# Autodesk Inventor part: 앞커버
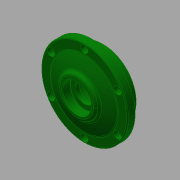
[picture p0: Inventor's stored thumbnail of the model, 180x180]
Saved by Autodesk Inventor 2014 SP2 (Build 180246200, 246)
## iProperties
Created: 2016-05
Part Number: 앞커버
Document SubType Name: Modeling
Designer: mduedu
Density: 2.71 g/cm^3
Material: 알루미늄 6061
Appearance: 진녹색
Author: mduedu
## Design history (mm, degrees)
sketch "스케치1"
  geometry: C1 r 35 at (0, 0); C2 r 45 at (0, 0); 1 further point
  constraints: 2 centre point, 2 coincident
  dimensions: "d33" = 90 diameter of C2; "d34" = 70 diameter of C1
extrude "돌출1" new body sketch "스케치1" distance "d0" = 8; taper "d1" = 0 deg
extrude "돌출2" join sketch "스케치1" distance "d2" = 8; taper "d3" = 0 deg; dims "d35" = 12, "d36" = 0
sketch "스케치5"
  geometry: L1 (-45, 8)-(45, 8) reference; L2 (0, 0)-(0, 15); L3 (-45, 0)-(45, 0) reference; L4 (35, 8)-(0, 8); A1 r 91 centre (0, -76) between (35, 8) and (0, 15)
  constraints: 4 end point, 3 point on line, 2 point on circle, 1 centre point, 1 midpoint, 1 perpendicular
  dimensions: "d37" = 35 distance from line of L2 L4.start; "d39" = 7 distance from line of L1 L2.end
revolve "회전2" sketch "스케치5" stored, may be unused: angle "d40" = 90 deg
node "작업 평면1"
sketch "스케치6"
  geometry: C1 r 20 at (0, 0); 1 further point
  constraints: 1 centre point, 1 coincident
  dimensions: "d42" = 40 diameter of C1
extrude "돌출4" join sketch "스케치6" stored distance "d43" = 10; taper "d44" = 0 deg
sketch "스케치4"
  geometry: L1 (0, -12)-(0, 16); L2 (-20, -12)-(-20, 0); L3 (-20, 0)-(-15, 0); L4 (-15, 0)-(-15, 3); L5 (-15, 3)-(-10, 3); L6 (-10, 3)-(-10, 7.5); L7 (-10, 7.5)-(-15, 7.5); L8 (-15, 7.5)-(-15, 16); L9 (35, -12)-(-35, -12) reference; L10 (-20, 16)-(20, 16) reference; 1 further point
  constraints: 16 end point, 6 parallel, 3 point on line, 2 midpoint, 1 perpendicular, 1 vertical
  dimensions: "d15" = 40 diameter of L2 L1; "d16" = 30 diameter of L8 L1; "d18" = 12 distance of L2.start L2.end; "d19" = 3 distance of L3.end L4.end; "d20" = 30 diameter of L4 L1; "d21" = 20 diameter of L6 L1; "d45" = 8.5 distance of L7.end L8.end
revolve "회전1" sketch "스케치4" stored, may be unused: angle "d22" = 90 deg
fillet "모깎기2" dims "d23" = 3
fillet "모깎기3" dims "d24" = 0.3
chamfer "모따기2" distance "d46" = 1; stored, may be unused: second distance "d47" = 2, angle "d48" = 45 deg
fillet "모깎기4" dims "d49" = 3
fillet "모깎기5" dims "d50" = 3
fillet "모깎기6" dims "d51" = 1
sketch "스케치7" dims "d52" = 80
  geometry: C1 r 35.595 at (0, 0) reference; C2 r 44 at (0, 0) reference; 7 further points
  constraints: 2 vertical alignment, 1 coincident, 9 other
  dimensions: "d55" = 360 deg dimension on C1.centre point (0, 40) (derived)
sketch "스케치8"
  geometry: 6 further points
  constraints: 6 other
hole "구멍2" sketch "스케치8" at (-34.641, 20), (-34.641, -20), (0, -40), (34.641, -20), (34.641, 20), (0, 40) diameter "d57" = 4.5; stored, may be unused: countersink angle "d61" = 90 deg, drill point angle "d63" = 0 deg; dims "d58" = 6, "d59" = 8, "d60" = 4.6, "d62" = 8
chamfer "모따기3" distance "d64" = 0.8; stored, may be unused: second distance "d65" = 2, angle "d66" = 30 deg
node "솔리드1"
other parameters: "d41" = 8
